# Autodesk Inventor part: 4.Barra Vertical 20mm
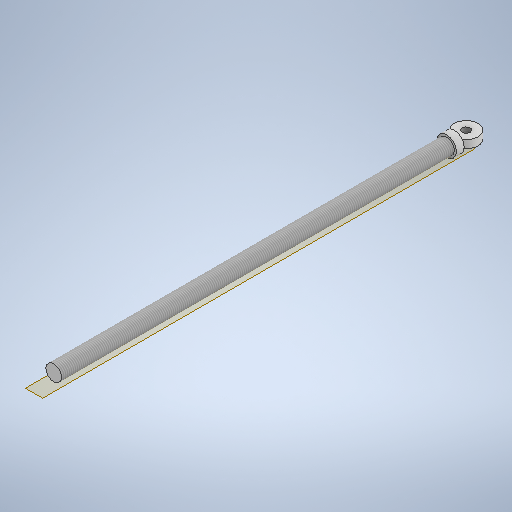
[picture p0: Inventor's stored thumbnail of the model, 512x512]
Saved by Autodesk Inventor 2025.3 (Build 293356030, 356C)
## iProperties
Created: 2025-10
Part Number: 4.Barra Vertical 20mm
Material: Genérico
Document SubType Name: Modeling
Designer: User
Density: 1 g/cm^3
Appearance: Valor por defecto
Author: User
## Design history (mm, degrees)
sketch "Boceto1"
  geometry: C1 r 10 at (0, 0); 1 further point
  constraints: 1 centre point
  dimensions: "d0" = 0 distance of point (0, 0) C1.centre; "d1" = 0 distance of point (0, 0) C1.centre; "d2" = 20 diameter of C1
extrude "Extrusión1" new body sketch "Boceto1" distance "d3" = 500; taper "d4" = 0 deg
node "Plano de trabajo1"
sketch "Boceto4"
  geometry: C1 r 10 at (0, 0) reference; C2 r 12.5 at (0, 0); 1 further point
  constraints: 1 centre point
  dimensions: "d6" = 0 distance of point (0, 0) C2.centre; "d7" = 0 distance of C2.centre point (0, 0); "d8" = 25 diameter of C2
extrude "Extrusión2" join sketch "Boceto4" distance "d9" = 10; taper "d10" = 0 deg
sketch "Boceto5"
  geometry: L1 (-12.5, -10)-(12.5, -10) reference; L2 (-12.5, 0)-(-12.5, -10) reference; C1 r 15 at (0, -25); 2 further points
  constraints: 1 centre point, 1 midpoint
  dimensions: "d11" = 15 distance from line of C1.centre L1; "d13" = 30 diameter of C1; "d14" = 0 horizontal distance of C1.centre point (0, -10)
extrude "Extrusión3" join sketch "Boceto5" stored distance "d15" = 10; taper "d16" = 0 deg
sketch "Boceto6"
  geometry: 4 further points
  constraints: 1 vertical alignment
  dimensions: "d17" = 0 distance of point (0, 0) point (0, 0); "d18" = 0 distance of point (0, 0) point (0, 0)
hole "Agujero1" sketch "Boceto6" at (0, 0) diameter "d19" = 10.106; stored, may be unused: countersink angle "d23" = 90 deg, drill point angle "d25" = 118 deg; dims "d20" = 24, "d21" = 4, "d22" = 2, "d24" = 8
feature "Rosca1" dims "d26" = 500, "d27" = 0
node "Sólido1"
